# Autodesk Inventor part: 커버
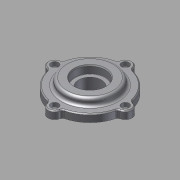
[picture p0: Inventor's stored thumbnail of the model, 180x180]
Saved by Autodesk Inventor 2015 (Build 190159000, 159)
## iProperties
Company: 한국ATC센터
Created: 2015-12
Part Number: 커버
Document SubType Name: Modeling
Designer: mdu
Density: 1 g/cm^3
Material: 일반
Appearance: 기본값
Author: mdu
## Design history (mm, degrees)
sketch "스케치1"
  geometry: C1 r 1.621 at (0, 6.75) reference; C2 r 1.621 at (-37, -30.25) reference; C3 r 1.621 at (0, -67.25) reference; C4 r 1.621 at (37, -30.25) reference; C5 r 10 at (0, -30.25) reference; C6 r 12 at (0, -30.25); C7 r 24.5 at (0, -30.25) reference; A1 r 3 centre (-38.77, -20.408) between (-38.239, -23.361) and (-35.862, -21.146) reference; A2 r 7 centre (-37, -30.25) between (-38.239, -23.361) and (-38.239, -37.139) reference; A3 r 3 centre (-38.77, -40.092) between (-35.862, -39.354) and (-38.239, -37.139) reference; A4 r 37 centre (0, -30.25) between (-35.862, -39.354) and (-9.104, -66.113) reference; A5 r 3 centre (-9.842, -69.02) between (-6.889, -68.489) and (-9.104, -66.113) reference; A6 r 7 centre (0, -67.25) between (-6.889, -68.489) and (6.889, -68.489) reference; A7 r 3 centre (9.842, -69.02) between (9.104, -66.112) and (6.889, -68.489) reference; A8 r 37 centre (0, -30.25) between (9.104, -66.112) and (35.863, -39.354) reference; A9 r 3 centre (38.77, -40.092) between (38.239, -37.139) and (35.863, -39.354) reference; A10 r 7 centre (37, -30.25) between (38.239, -37.139) and (38.239, -23.361) reference; A11 r 3 centre (38.77, -20.408) between (35.863, -21.146) and (38.239, -23.361) reference; A12 r 37 centre (0, -30.25) between (35.863, -21.146) and (9.104, 5.612) reference; A13 r 3 centre (9.842, 8.52) between (6.889, 7.989) and (9.104, 5.612) reference; A14 r 7 centre (0, 6.75) between (6.889, 7.989) and (-6.889, 7.989) reference; A15 r 3 centre (-9.842, 8.52) between (-9.104, 5.612) and (-6.889, 7.989) reference; A16 r 37 centre (0, -30.25) between (-9.104, 5.612) and (-35.862, -21.146) reference; 1 further point
  constraints: 1 centre point, 1 coincident
  dimensions: "d2" = 2 radial gap between concentric circles of C6 C5
extrude "돌출1" new body sketch "스케치1" distance "d0" = 8; taper "d1" = 0 deg
sketch "스케치2"
  geometry: C1 r 23.5 at (0, -30.25) reference; C2 r 12 at (0, -30.25) reference; 1 further point
extrude "돌출2" join sketch "스케치2" distance "d4" = 5; taper "d5" = 0 deg
sketch "스케치3"
  geometry: C1 r 23.5 at (0, 0) reference; C2 r 20.5 at (0, 0); 1 further point
  constraints: 1 centre point
  dimensions: "d6" = 3 radial gap between concentric circles of C2 C1
node "작업 평면1"
extrude "돌출3" join sketch "스케치3" stored distance "d7" = 5; taper "d8" = 0 deg
fillet "모깎기1" dims "d9" = 3
sketch "스케치4"
  geometry: C1 r 12 at (0, -30.25) reference; C2 r 27 at (0, -30.25); 1 further point
  constraints: 1 centre point
  dimensions: "d10" = 15 radial gap between concentric circles of C1 C2
extrude "돌출4" join sketch "스케치4" distance "d11" = 7; taper "d12" = 0 deg
fillet "모깎기2" dims "d13" = 3
chamfer "모따기1" distance "d14" = 1; stored, may be unused: second distance "d15" = 2, angle "d16" = 45 deg
node "작업점1"
  node "작업축1"
chamfer "모따기2" distance "d24" = 1; stored, may be unused: second distance "d25" = 2, angle "d26" = 45 deg
hole "구멍6" diameter "d43" = 4.5; stored, may be unused: countersink angle "d47" = 90 deg, drill point angle "d49" = 118 deg; dims "d41" = 10, "d42" = 10, "d44" = 6, "d45" = 8, "d46" = 4.4, "d48" = 8
sketch "스케치8"
  geometry: C1 r 12 at (0, 0) reference; C2 r 16 at (0, 0); 1 further point
  constraints: 1 centre point, 1 coincident
  dimensions: "d53" = 32 diameter of C2
extrude "돌출5" cut sketch "스케치8" distance "d54" = 8.3; taper "d55" = 0 deg
fillet "모깎기3" dims "d56" = 0.3
chamfer "모따기3" distance "d57" = 1.2; stored, may be unused: second distance "d58" = 2, angle "d59" = 30 deg
node "솔리드1"
pattern_circular "원형 패턴1" dims angle "d51" = 360 deg
node "참조1"
node "참조2"
